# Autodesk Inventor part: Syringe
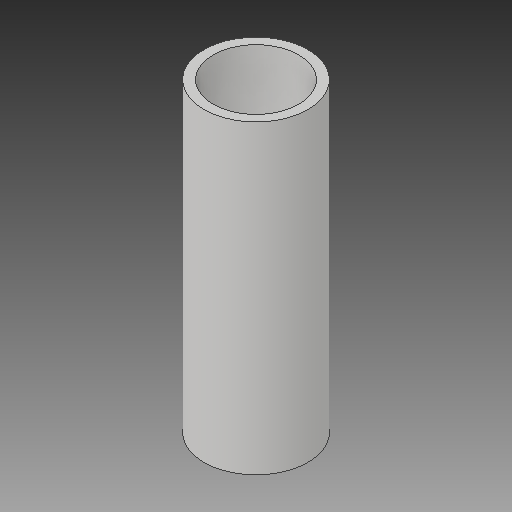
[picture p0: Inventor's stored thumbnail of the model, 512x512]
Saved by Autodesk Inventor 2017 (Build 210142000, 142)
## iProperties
Created: 2020-03
Part Number: Syringe
Material: Generic
Document SubType Name: Modeling
Designer: user
Density: 1 g/cm^3
Appearance: Default
Mass: 3.80761 g
Surface Area: 51.9462 cm^2
Volume: 3.80761 cm^3
Author: user
Revision Number: ANY
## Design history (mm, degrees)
feature "Revolve1"
body "Solid1"
